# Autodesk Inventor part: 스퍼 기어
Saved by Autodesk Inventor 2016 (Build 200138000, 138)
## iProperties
Created: 2024-08
Part Number: 스퍼 기어
Material: 일반
Document SubType Name: Modeling
Designer: pc-2
Density: 1 g/cm^3
Appearance: 기본값
Author: jhkim
Sending System: Autodesk Inventor 2025
Preprocessor: ST-DEVELOPER v20
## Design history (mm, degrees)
node "스퍼 기어1"
node "솔리드2"
node "솔리드1"
